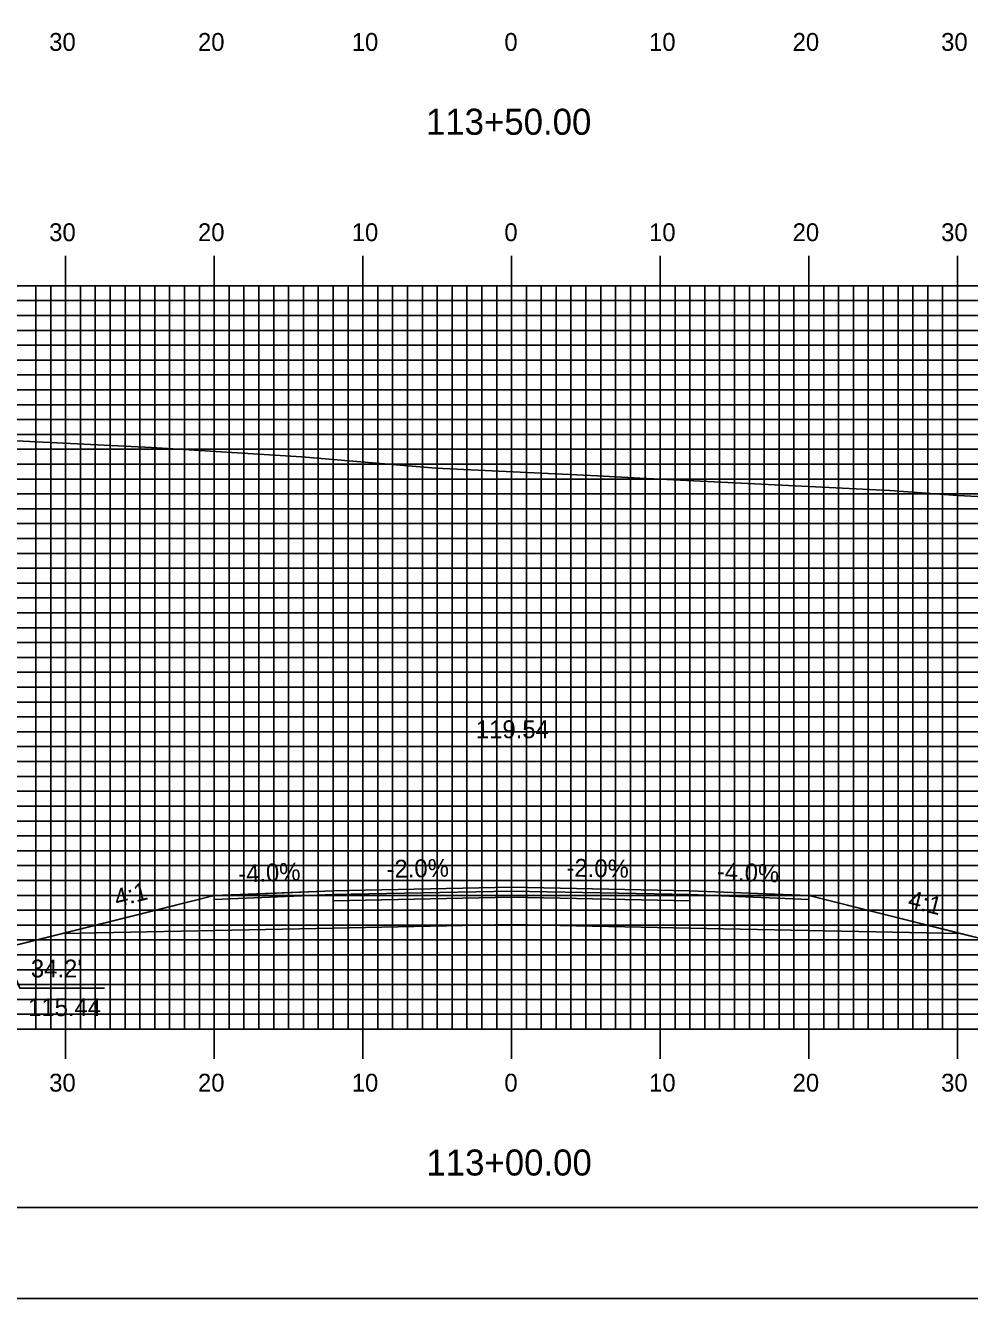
# Model space of a CAD drawing. Extents: x 1770448 to 1770792, y 442591 to 442811.
# Drawn here: x 1770581.3 to 1770644.9, y 442590.5 to 442676.2 of the extents above; entities that cross this region are included whole.
import ezdxf

# ---------------------------------------------------------------- set-up
doc = ezdxf.new("R2010")
doc.units = 0
for name, color, linetype in [('ANNOTATION', 7, 'Continuous'), ('BORDER', 7, 'Continuous'), ('D_Roadway_Centerline', 7, 'Continuous'), ('D_Roadway_Centerline_Text', 7, 'Continuous'), ('D_Roadway_Edge_Shoulder', 7, 'Continuous'), ('D_Roadway_Edge_TW', 7, 'Continuous'), ('D_Roadway_Pavement', 7, 'Continuous'), ('D_Roadway_SlopeLines', 7, 'Continuous'), ('D_Roadway_SubGrade', 7, 'Continuous'), ('H_V ANNOTATION', 7, 'Continuous'), ('MAJOR', 7, 'Continuous'), ('MINOR', 7, 'Continuous'), ('PLOT BOUNDARY', 7, 'Continuous'), ('S_Roadway_Centerline', 7, 'Continuous')]:
    doc.layers.add(name, color=color, linetype=linetype)

msp = doc.modelspace()

# ---------------------------------------------------------------- linework, layer by layer
at = {"layer": 'ANNOTATION'}
msp.add_lwpolyline([(1770586.666, 442611.417), (1770580.975, 442611.417), (1770579.867, 442614.102)], dxfattribs=at)
at = {"layer": 'BORDER'}
msp.add_lwpolyline([(1770464.441, 442596.665), (1770784.441, 442596.665), (1770784.441, 442806.665), (1770464.441, 442806.665)], close=True, dxfattribs=at)
at = {"layer": 'D_Roadway_Centerline'}
msp.add_lwpolyline([(1770521.071, 442651.82), (1770522.32, 442651.634), (1770523.571, 442651.263), (1770524.206, 442650.981), (1770524.821, 442650.707), (1770526.07, 442649.966), (1770526.074, 442649.964), (1770556.863, 442629.438), (1770579.867, 442614.102), (1770581.245, 442614.447), (1770583.867, 442615.102), (1770590.674, 442616.804), (1770594.041, 442617.646), (1770597.125, 442617.77), (1770602.041, 442617.966), (1770614.041, 442618.206), (1770626.041, 442617.966), (1770634.042, 442617.646), (1770644.215, 442615.102), (1770648.215, 442614.102)], dxfattribs=at)
at = {"layer": 'D_Roadway_Edge_Shoulder'}
for points in [[(1770602.041, 442617.966), (1770594.041, 442617.646), (1770594.041, 442617.396), (1770602.041, 442617.716)], [(1770626.041, 442617.966), (1770634.042, 442617.646), (1770634.042, 442617.396), (1770626.041, 442617.716)]]:
    msp.add_lwpolyline(points, close=True, dxfattribs=at)
at = {"layer": 'D_Roadway_Edge_TW'}
msp.add_lwpolyline([(1770602.041, 442617.716), (1770602.041, 442617.966), (1770614.041, 442618.206), (1770626.041, 442617.966), (1770626.041, 442617.716), (1770614.041, 442617.956)], close=True, dxfattribs=at)
at = {"layer": 'D_Roadway_Pavement'}
msp.add_lwpolyline([(1770602.041, 442617.299), (1770602.041, 442617.716), (1770614.041, 442617.956), (1770626.041, 442617.716), (1770626.041, 442617.299), (1770614.041, 442617.539)], close=True, dxfattribs=at)
at = {"layer": 'D_Roadway_SlopeLines'}
for points in [[(1770594.041, 442617.646), (1770579.867, 442614.102)], [(1770634.042, 442617.646), (1770648.215, 442614.102)]]:
    msp.add_lwpolyline(points, dxfattribs=at)
at = {"layer": 'D_Roadway_SubGrade'}
msp.add_lwpolyline([(1770602.041, 442615.466), (1770583.867, 442615.102), (1770594.041, 442617.646), (1770594.041, 442617.396), (1770602.041, 442617.716), (1770614.041, 442617.956), (1770626.041, 442617.716), (1770634.042, 442617.396), (1770634.042, 442617.646), (1770644.215, 442615.102), (1770626.041, 442615.466), (1770614.041, 442615.706)], close=True, dxfattribs=at)
at = {"layer": 'MAJOR'}
for p, q in [((1770584.041, 442660.669), (1770584.041, 442658.665)), ((1770594.041, 442660.669), (1770594.041, 442658.665)), ((1770604.041, 442660.669), (1770604.041, 442658.665)), ((1770614.041, 442660.669), (1770614.041, 442658.665)), ((1770624.041, 442660.669), (1770624.041, 442658.665)), ((1770634.041, 442660.669), (1770634.041, 442658.665)), ((1770644.041, 442660.669), (1770644.041, 442658.665)), ((1770474.041, 442658.665), (1770754.041, 442658.665)), ((1770474.041, 442658.665), (1770754.041, 442658.665)), ((1770584.041, 442608.665), (1770584.041, 442658.665)), ((1770594.041, 442608.665), (1770594.041, 442658.665)), ((1770604.041, 442608.665), (1770604.041, 442658.665)), ((1770614.041, 442608.665), (1770614.041, 442658.665)), ((1770624.041, 442608.665), (1770624.041, 442658.665)), ((1770634.041, 442608.665), (1770634.041, 442658.665)), ((1770644.041, 442608.665), (1770644.041, 442658.665)), ((1770474.041, 442653.665), (1770754.041, 442653.665)), ((1770474.041, 442648.665), (1770754.041, 442648.665)), ((1770474.041, 442643.665), (1770754.041, 442643.665)), ((1770474.041, 442638.665), (1770754.041, 442638.665)), ((1770474.041, 442633.665), (1770754.041, 442633.665)), ((1770474.041, 442628.665), (1770754.041, 442628.665)), ((1770474.041, 442623.665), (1770754.041, 442623.665)), ((1770474.041, 442618.665), (1770754.041, 442618.665)), ((1770474.041, 442613.665), (1770754.041, 442613.665)), ((1770474.041, 442608.665), (1770754.041, 442608.665)), ((1770474.041, 442608.665), (1770754.041, 442608.665)), ((1770584.041, 442606.661), (1770584.041, 442608.665)), ((1770594.041, 442606.661), (1770594.041, 442608.665)), ((1770604.041, 442606.661), (1770604.041, 442608.665)), ((1770614.041, 442606.661), (1770614.041, 442608.665)), ((1770624.041, 442606.661), (1770624.041, 442608.665)), ((1770634.041, 442606.661), (1770634.041, 442608.665)), ((1770644.041, 442606.661), (1770644.041, 442608.665))]:
    msp.add_line(p, q, dxfattribs=at)
at = {"layer": 'MINOR'}
for p, q in [((1770582.041, 442608.665), (1770582.041, 442658.665)), ((1770583.041, 442608.665), (1770583.041, 442658.665)), ((1770585.041, 442608.665), (1770585.041, 442658.665)), ((1770586.041, 442608.665), (1770586.041, 442658.665)), ((1770587.041, 442608.665), (1770587.041, 442658.665)), ((1770588.041, 442608.665), (1770588.041, 442658.665)), ((1770589.041, 442608.665), (1770589.041, 442658.665)), ((1770590.041, 442608.665), (1770590.041, 442658.665)), ((1770591.041, 442608.665), (1770591.041, 442658.665)), ((1770592.041, 442608.665), (1770592.041, 442658.665)), ((1770593.041, 442608.665), (1770593.041, 442658.665)), ((1770595.041, 442608.665), (1770595.041, 442658.665)), ((1770596.041, 442608.665), (1770596.041, 442658.665)), ((1770597.041, 442608.665), (1770597.041, 442658.665)), ((1770598.041, 442608.665), (1770598.041, 442658.665)), ((1770599.041, 442608.665), (1770599.041, 442658.665)), ((1770600.041, 442608.665), (1770600.041, 442658.665)), ((1770601.041, 442608.665), (1770601.041, 442658.665)), ((1770602.041, 442608.665), (1770602.041, 442658.665)), ((1770603.041, 442608.665), (1770603.041, 442658.665)), ((1770605.041, 442608.665), (1770605.041, 442658.665)), ((1770606.041, 442608.665), (1770606.041, 442658.665)), ((1770607.041, 442608.665), (1770607.041, 442658.665)), ((1770608.041, 442608.665), (1770608.041, 442658.665)), ((1770609.041, 442608.665), (1770609.041, 442658.665)), ((1770610.041, 442608.665), (1770610.041, 442658.665)), ((1770611.041, 442608.665), (1770611.041, 442658.665)), ((1770612.041, 442608.665), (1770612.041, 442658.665)), ((1770613.041, 442608.665), (1770613.041, 442658.665)), ((1770615.041, 442608.665), (1770615.041, 442658.665)), ((1770616.041, 442608.665), (1770616.041, 442658.665)), ((1770617.041, 442608.665), (1770617.041, 442658.665)), ((1770618.041, 442608.665), (1770618.041, 442658.665)), ((1770619.041, 442608.665), (1770619.041, 442658.665)), ((1770620.041, 442608.665), (1770620.041, 442658.665)), ((1770621.041, 442608.665), (1770621.041, 442658.665)), ((1770622.041, 442608.665), (1770622.041, 442658.665)), ((1770623.041, 442608.665), (1770623.041, 442658.665)), ((1770625.041, 442608.665), (1770625.041, 442658.665)), ((1770626.041, 442608.665), (1770626.041, 442658.665)), ((1770627.041, 442608.665), (1770627.041, 442658.665)), ((1770628.041, 442608.665), (1770628.041, 442658.665)), ((1770629.041, 442608.665), (1770629.041, 442658.665)), ((1770630.041, 442608.665), (1770630.041, 442658.665)), ((1770631.041, 442608.665), (1770631.041, 442658.665)), ((1770632.041, 442608.665), (1770632.041, 442658.665)), ((1770633.041, 442608.665), (1770633.041, 442658.665)), ((1770635.041, 442608.665), (1770635.041, 442658.665)), ((1770636.041, 442608.665), (1770636.041, 442658.665)), ((1770637.041, 442608.665), (1770637.041, 442658.665)), ((1770638.041, 442608.665), (1770638.041, 442658.665)), ((1770639.041, 442608.665), (1770639.041, 442658.665)), ((1770640.041, 442608.665), (1770640.041, 442658.665)), ((1770641.041, 442608.665), (1770641.041, 442658.665)), ((1770642.041, 442608.665), (1770642.041, 442658.665)), ((1770643.041, 442608.665), (1770643.041, 442658.665)), ((1770474.041, 442657.665), (1770754.041, 442657.665)), ((1770474.041, 442656.665), (1770754.041, 442656.665)), ((1770474.041, 442655.665), (1770754.041, 442655.665)), ((1770474.041, 442654.665), (1770754.041, 442654.665)), ((1770474.041, 442652.665), (1770754.041, 442652.665)), ((1770474.041, 442651.665), (1770754.041, 442651.665)), ((1770474.041, 442650.665), (1770754.041, 442650.665)), ((1770474.041, 442649.665), (1770754.041, 442649.665)), ((1770474.041, 442647.665), (1770754.041, 442647.665)), ((1770474.041, 442646.665), (1770754.041, 442646.665)), ((1770474.041, 442645.665), (1770754.041, 442645.665)), ((1770474.041, 442644.665), (1770754.041, 442644.665)), ((1770474.041, 442642.665), (1770754.041, 442642.665)), ((1770474.041, 442641.665), (1770754.041, 442641.665)), ((1770474.041, 442640.665), (1770754.041, 442640.665)), ((1770474.041, 442639.665), (1770754.041, 442639.665)), ((1770474.041, 442637.665), (1770754.041, 442637.665)), ((1770474.041, 442636.665), (1770754.041, 442636.665)), ((1770474.041, 442635.665), (1770754.041, 442635.665)), ((1770474.041, 442634.665), (1770754.041, 442634.665)), ((1770474.041, 442632.665), (1770754.041, 442632.665)), ((1770474.041, 442631.665), (1770754.041, 442631.665)), ((1770474.041, 442630.665), (1770754.041, 442630.665)), ((1770474.041, 442629.665), (1770754.041, 442629.665)), ((1770474.041, 442627.665), (1770754.041, 442627.665)), ((1770474.041, 442626.665), (1770754.041, 442626.665)), ((1770474.041, 442625.665), (1770754.041, 442625.665)), ((1770474.041, 442624.665), (1770754.041, 442624.665)), ((1770474.041, 442622.665), (1770754.041, 442622.665)), ((1770474.041, 442621.665), (1770754.041, 442621.665)), ((1770474.041, 442620.665), (1770754.041, 442620.665)), ((1770474.041, 442619.665), (1770754.041, 442619.665)), ((1770474.041, 442617.665), (1770754.041, 442617.665)), ((1770474.041, 442616.665), (1770754.041, 442616.665)), ((1770474.041, 442615.665), (1770754.041, 442615.665)), ((1770474.041, 442614.665), (1770754.041, 442614.665)), ((1770474.041, 442612.665), (1770754.041, 442612.665)), ((1770474.041, 442611.665), (1770754.041, 442611.665)), ((1770474.041, 442610.665), (1770754.041, 442610.665)), ((1770474.041, 442609.665), (1770754.041, 442609.665))]:
    msp.add_line(p, q, dxfattribs=at)
at = {"layer": 'PLOT BOUNDARY'}
msp.add_lwpolyline([(1770448.254, 442590.547), (1770788.254, 442590.547), (1770788.254, 442810.547), (1770448.254, 442810.547)], close=True, dxfattribs=at)
at = {"layer": 'S_Roadway_Centerline'}
msp.add_lwpolyline([(1770474.041, 442652.821), (1770480.242, 442652.875), (1770482.089, 442652.902), (1770488.882, 442652.851), (1770500.075, 442652.584), (1770501.784, 442652.524), (1770505.624, 442652.39), (1770521.011, 442651.825), (1770523.955, 442651.605), (1770528.346, 442651.404), (1770536.61, 442650.868), (1770541.267, 442650.887), (1770560.703, 442649.56), (1770560.709, 442649.559), (1770572.501, 442648.868), (1770580.263, 442648.266), (1770589.826, 442647.784), (1770599.917, 442647.161), (1770608.957, 442646.389), (1770619.82, 442645.879), (1770622.677, 442645.714), (1770639.496, 442644.896), (1770644.071, 442644.564), (1770651.96, 442644.146)], dxfattribs=at)

# ---------------------------------------------------------------- texts
at = {"layer": 'ANNOTATION'}
for s, rotation, p in [('-2.0%', 1.14578, (1770605.647, 442618.839)), ('-2.0%', 358.85422, (1770617.727, 442618.933)), ('-4.0%', 2.29053, (1770595.673, 442618.513)), ('-4.0%', 357.70962, (1770627.833, 442618.696)), ('4:1', 14.03913, (1770587.489, 442616.87)), ('4:1', 345.96156, (1770640.634, 442616.859))]:
    msp.add_text(s, height=1.2, rotation=rotation, dxfattribs=at).set_placement(p)
for s, p in [("34.2'", (1770581.709, 442612.143)), ('115.44', (1770581.522, 442609.543))]:
    msp.add_text(s, height=1.2, dxfattribs=at).set_placement(p)
at = {"layer": 'D_Roadway_Centerline'}
for s, p in [('C', (1770614.036, 442618.206)), ('L', (1770614.041, 442618.199))]:
    msp.add_text(s, height=0.0146, dxfattribs=at).set_placement(p)
at = {"layer": 'D_Roadway_Centerline_Text'}
msp.add_text('119.54', height=1.2, dxfattribs=at).set_placement((1770611.644, 442628.236))
at = {"layer": 'H_V ANNOTATION'}
for s, height, p in [('30', 1.2, (1770582.939, 442674.465)), ('20', 1.2, (1770592.949, 442674.465)), ('10', 1.2, (1770603.292, 442674.465)), ('0', 1.2, (1770613.559, 442674.465)), ('10', 1.2, (1770623.292, 442674.465)), ('20', 1.2, (1770632.949, 442674.465)), ('30', 1.2, (1770642.939, 442674.465)), ('113+50.00', 1.75, (1770608.283, 442668.821)), ('30', 1.2, (1770582.939, 442661.665)), ('20', 1.2, (1770592.949, 442661.665)), ('10', 1.2, (1770603.292, 442661.665)), ('0', 1.2, (1770613.559, 442661.665)), ('10', 1.2, (1770623.292, 442661.665)), ('20', 1.2, (1770632.949, 442661.665)), ('30', 1.2, (1770642.939, 442661.665)), ('30', 1.2, (1770582.939, 442604.465)), ('20', 1.2, (1770592.949, 442604.465)), ('10', 1.2, (1770603.292, 442604.465)), ('0', 1.2, (1770613.559, 442604.465)), ('10', 1.2, (1770623.292, 442604.465)), ('20', 1.2, (1770632.949, 442604.465)), ('30', 1.2, (1770642.939, 442604.465)), ('113+00.00', 1.75, (1770608.314, 442598.821))]:
    msp.add_text(s, height=height, dxfattribs=at).set_placement(p)

doc.saveas('drawing.dxf')
